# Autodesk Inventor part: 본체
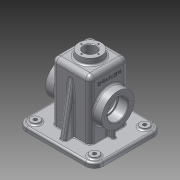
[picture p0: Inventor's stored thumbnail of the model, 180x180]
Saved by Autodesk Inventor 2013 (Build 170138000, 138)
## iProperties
Created: 2016-01
Part Number: 본체
Material: 알루미늄 6061
Document SubType Name: Modeling
Designer: User
Density: 1 g/cm^3
Mass: 298.56 g
Surface Area: 910.359 cm^2
Volume: 298.56 cm^3
Author: User
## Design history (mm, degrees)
sketch "스케치1"
  geometry: L1 (-32.5, 55)-(-32.5, -55); L2 (-32.5, -55)-(32.5, -55); L3 (32.5, -55)-(32.5, 55); L4 (32.5, 55)-(-32.5, 55); 3 further points
  constraints: 8 end point, 2 midpoint, 2 vertical, 1 horizontal alignment, 1 parallel, 1 perpendicular, 1 vertical alignment
  dimensions: "d0" = 110 distance of L1.start L1.end; "d1" = 65 distance of L1.end L2.end
extrude "돌출1" new body sketch "스케치1" stored distance "d2" = 65; taper "d3" = 0 deg
sketch "스케치2"
  geometry: L1 (65, -65)-(65, 0) reference; L2 (0, 0)-(65, 0) reference; L3 (0, -65)-(0, 0) reference; L4 (65, -65)-(0, -65) reference; L5 (-32.5, 25)-(97.5, 25); L6 (97.5, 25)-(97.5, -90); L7 (97.5, -90)-(-32.5, -90); L8 (-32.5, -90)-(-32.5, 25); 3 further points
  constraints: 8 end point, 2 midpoint, 2 parallel, 1 horizontal, 1 horizontal alignment, 1 perpendicular, 1 vertical alignment
  dimensions: "d4" = 130 distance of L6.end L7.end; "d5" = 115 distance of L5.end L6.end
extrude "돌출2" join sketch "스케치2" distance "d6" = 10; taper "d7" = 0 deg
sketch "스케치3"
  geometry: L1 (37.5, -30)-(92.5, -30); L2 (92.5, -30)-(92.5, -85); L3 (92.5, -85)-(37.5, -85); L4 (37.5, -85)-(37.5, -30); 3 further points
  constraints: 8 end point, 2 midpoint, 2 parallel, 1 horizontal, 1 horizontal alignment, 1 perpendicular, 1 vertical alignment
  dimensions: "d8" = 55 distance of L2.end L3.end; "d9" = 55 distance of L1.end L2.end
extrude "돌출3" cut sketch "스케치3" distance "d10" = 105; taper "d11" = 0 deg
sketch "스케치4"
  geometry: L1 (-25, -110)-(90, -110) reference; C1 r 27.5 at (32.5, -55); 1 further point
  constraints: 1 centre point, 1 coincident
  dimensions: "d12" = 27.5 radius of C1; "d13" = 55 distance from line of L1 C1.centre
extrude "돌출4" join sketch "스케치4" distance "d14" = 15; taper "d15" = 0 deg
hole "구멍1" diameter "d18" = 35; stored, may be unused: countersink angle "d22" = 90 deg, drill point angle "d24" = 0 deg; dims "d16" = 10, "d17" = 10, "d19" = 6, "d20" = 4, "d21" = 2, "d23" = 17
hole "구멍3" diameter "d36" = 30; stored, may be unused: countersink angle "d40" = 90 deg, drill point angle "d42" = 0 deg; dims "d34" = 10, "d35" = 10, "d37" = 6, "d38" = 4, "d39" = 2, "d41" = 17
sketch "스케치5"
  geometry: C1 r 20 at (32.5, 32.5); 1 further point
  constraints: 1 centre point, 1 coincident
  dimensions: "d43" = 20 radius of C1
extrude "돌출5" join sketch "스케치5" distance "d44" = 10; taper "d45" = -5 deg
hole "구멍4" diameter "d48" = 21; stored, may be unused: countersink angle "d52" = 90 deg, drill point angle "d54" = 0 deg; dims "d46" = 10, "d47" = 10, "d49" = 6, "d50" = 4, "d51" = 2, "d53" = 17
fillet "모깎기1" dims "d55" = 15
sketch "스케치6"
  geometry: C1 r 7.5 at (-17.5, 75); C2 r 7.5 at (-17.5, -10); A1 r 15 centre (-17.5, 75) between (-17.5, 90) and (-32.5, 75) reference; A2 r 15 centre (-17.5, -10) between (-32.5, -10) and (-17.5, -25) reference; 1 further point
  constraints: 2 centre point, 2 coincident
  dimensions: "d56" = 7.5 radius of C1; "d57" = 7.5 radius of C2
extrude "돌출6" join sketch "스케치6" distance "d58" = 3; taper "d59" = 0 deg
hole "구멍5" diameter "d62" = 6; stored, may be unused: countersink angle "d66" = 90 deg, drill point angle "d68" = 0 deg; dims "d60" = 10, "d61" = 10, "d63" = 6, "d64" = 4, "d65" = 2, "d67" = 17
hole "구멍6" diameter "d71" = 6; stored, may be unused: countersink angle "d75" = 90 deg, drill point angle "d77" = 0 deg; dims "d69" = 10, "d70" = 10, "d72" = 6, "d73" = 4, "d74" = 2, "d76" = 17
sketch "스케치7"
  geometry: L1 (100, 0)-(0, 0) reference; L2 (115, 100)-(115, 15) reference; L3 (0, 115)-(100, 115) reference; L4 (-15, 15)-(-15, 100) reference; L5 (110, 100)-(110, 15); L6 (100, 5)-(0, 5); L7 (-10, 15)-(-10, 100); L8 (0, 110)-(100, 110); A1 r 15 centre (0, 15) between (-15, 15) and (0, 0) reference; A2 r 15 centre (100, 15) between (100, 0) and (115, 15) reference; A3 r 15 centre (100, 100) between (115, 100) and (100, 115) reference; A4 r 15 centre (0, 100) between (0, 115) and (-15, 100) reference; A5 r 10 centre (100, 100) between (110, 100) and (100, 110); A6 r 10 centre (100, 15) between (100, 5) and (110, 15); A7 r 10 centre (0, 15) between (-10, 15) and (0, 5); A8 r 10 centre (0, 100) between (0, 110) and (-10, 100); 1 further point
  constraints: 8 end point, 8 point on circle, 4 centre point, 7 other
  dimensions: "d78" = 5 distance between parallel lines of L8 L3
extrude "돌출7" cut sketch "스케치7" distance "d79" = 2; taper "d80" = 0 deg
sketch "스케치8"
  geometry: L1 (-45, -47.5)-(40.069, -32.5); L2 (-45, -32.5)-(55, -32.5) reference; L3 (-45, -35)-(-45, -50) reference; L4 (-45, -42.5)-(-45, -57.5) reference; L5 (55, 32.5)-(-45, 32.5) reference; L6 (-45, 50)-(-45, 35) reference; L7 (-45, 57.5)-(-45, 42.5) reference; 1 further point
  constraints: 2 end point, 2 point on line
  dimensions: "d82" = 10 deg angle of L2 L1; "d83" = 10 distance of L4.end L1.start
feature "리브1" sketch "스케치8" dims "d84" = 1, "d85" = 10, "d86" = 0, "d87" = 0, "d88" = 1, "d89" = 1
sketch "스케치9"
  geometry: L1 (42.5, -27.5)-(42.5, -45); L2 (32.5, -27.5)-(47.5, -27.5) reference; L3 (50, -45)-(-50, -45) reference; L4 (27.5, -55)-(27.5, 50) reference; 1 further point
  constraints: 2 end point, 2 point on line, 1 vertical
  dimensions: "d90" = 15 distance between parallel lines of L1 L4
feature "리브2" sketch "스케치9" dims "d91" = 1, "d92" = 6, "d93" = 0, "d94" = 0, "d95" = 1, "d96" = 1
sketch "스케치10"
  geometry: C1 r 17.5 at (0, 0) reference; 1 further point
  constraints: 1 vertical alignment
  dimensions: "d97" = 21 distance of C1.centre point (0, 21)
hole "구멍7" sketch "스케치10" at (0, 21) diameter "d98" = 3.242; stored, may be unused: countersink angle "d102" = 90 deg, drill point angle "d104" = 118 deg; dims "d99" = 8, "d100" = 4, "d101" = 2, "d103" = 10
sketch "스케치11"
  geometry: C1 r 19.125 at (0, 0) reference; 1 further point
  constraints: 1 vertical alignment
  dimensions: "d108" = 14.5 distance of C1.centre point (0, 14.5)
hole "구멍8" sketch "스케치11" at (0, 14.5) diameter "d109" = 2.459; stored, may be unused: countersink angle "d113" = 90 deg, drill point angle "d115" = 118 deg; dims "d110" = 7, "d111" = 4, "d112" = 2, "d114" = 9
fillet "모깎기2" dims "d119" = 8
fillet "모깎기3" dims "d120" = 0.3
fillet "모깎기4" dims "d121" = 3
fillet "모깎기5" dims "d122" = 3
fillet "모깎기8" dims "d125" = 3
sketch "스케치12"
  geometry: L1 (-8, 0)-(-8, -92) reference; L2 (5.375, 18)-(43.625, 18) reference; 2 further points
  constraints: 1 other
  dimensions: "d127" = 32.5 distance from line of point (24.5, -8) L1; "d128" = 26 distance from line of L2 point (24.5, -8)
feature "엠보싱1" sketch "스케치12" dims "d7" = 0, "d129" = 0.5, "d130" = 0
fillet "모깎기10" dims "d131" = 3
fillet "모깎기11" dims "d132" = 3
fillet "모깎기12" dims "d133" = 3
fillet "모깎기13" dims "d134" = 1
chamfer "모따기1" distance "d135" = 1; stored, may be unused: second distance "d136" = 2, angle "d137" = 45 deg
node "솔리드1"
mirror "대칭1"
mirror "대칭2"
mirror "대칭3"
mirror "대칭4"
pattern_circular "원형 패턴1" dims angle "d106" = 360 deg
mirror "대칭5"
pattern_circular "원형 패턴2" dims angle "d117" = 360 deg
